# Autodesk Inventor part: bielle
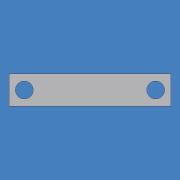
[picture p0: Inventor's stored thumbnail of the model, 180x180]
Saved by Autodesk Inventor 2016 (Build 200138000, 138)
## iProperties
Shininess: 64.0
Length Units: 11269
Angle Units: 11279
Time Units: 11290
Mass Units: 11283
Length Display Precision: 3
Angle Display Precision: 2
Compacted: True
Part Number: bielle
Document SubType Name: Modeling
Created: 2003-07
Material: Générique
Designer: trameau
Density: 1 g/cm^3
Appearance: Par défaut
Density: 0.0
Volumn: 0.0
Area: 0.0
PropertySet Name: Model Information
Control State: 0
Master: False
Checked Out: False
Author: trameau
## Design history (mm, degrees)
sketch "Esquisse1"
  geometry: L1 (-33.192, 10.926)-(56.808, 10.926); L2 (56.808, 10.926)-(56.808, -7.074); L3 (56.808, -7.074)-(-33.192, -7.074); L4 (-33.192, -7.074)-(-33.192, 10.926)
  constraints: 8 end point, 2 parallel, 1 horizontal, 1 perpendicular
  dimensions: "d0" = 90 distance between parallel lines of L2 L4; "d1" = 18 distance between parallel lines of L1 L3
extrude "Extrusion1" new body sketch "Esquisse1" distance "d2" = 10; taper "d3" = 0 deg
sketch "Esquisse2"
  geometry: L1 (56.808, 10.926)-(56.808, -7.074) reference; L2 (-33.192, -7.074)-(-33.192, 10.926) reference; 2 further points
  dimensions: "d4" = 8.5 distance from line of L2 point (-24.692, 1.926) (= d5); "d5" = 8.5 distance from line of L1 point (48.308, 1.926)
hole "Perçage1" sketch "Esquisse2" at (-24.692, 1.926), (48.308, 1.926) diameter "d6" = 10; stored, may be unused: countersink angle "d10" = 82 deg, drill point angle "d12" = 118 deg; dims "d7" = 6, "d8" = 4, "d9" = 2, "d11" = 8
node "Solide1"
node "Corps solides"
node "Corps surfaciques"
